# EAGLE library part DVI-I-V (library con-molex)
CONNECTOR MiroCross(TM)-DVI i/0 plug and receptacle connector system (scart)
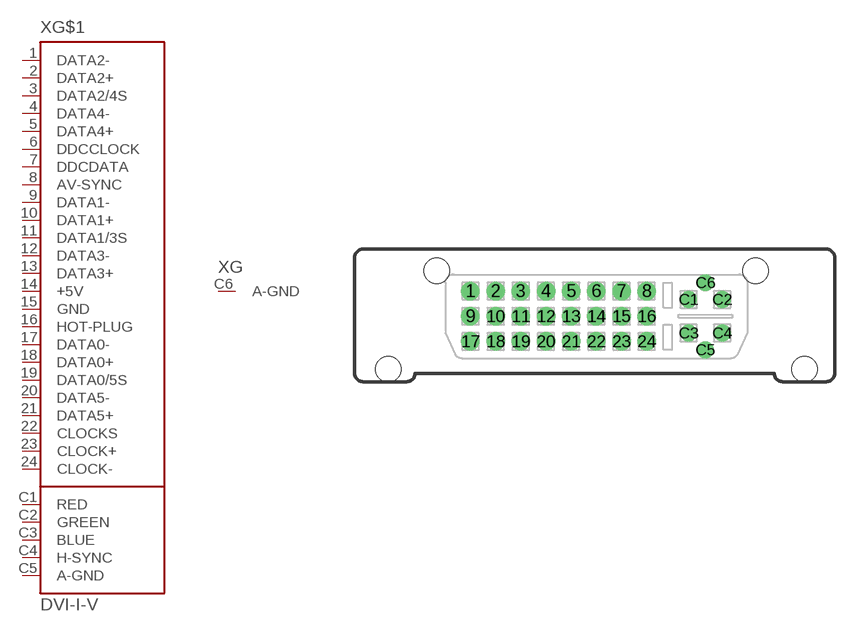
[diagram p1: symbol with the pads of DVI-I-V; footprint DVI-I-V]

Designator prefix X; gates G$1=DVI-I G=AGND

## DVI-I-V (OC_FARNELL: unknown; OC_NEWARK: unknown)  [DVI-I-V]
1  G$1:DATA2-  pas
2  G$1:DATA2+  pas
3  G$1:DATA2/4S  pas
4  G$1:DATA4-  pas
5  G$1:DATA4+  pas
6  G$1:DDCCLOCK  pas
7  G$1:DDCDATA  pas
8  G$1:AV-SYNC  pas
9  G$1:DATA1-  pas
10  G$1:DATA1+  pas
11  G$1:DATA1/3S  pas
12  G$1:DATA3-  pas
13  G$1:DATA3+  pas
14  G$1:+5V  pwr
15  G$1:GND  pwr
16  G$1:HOT-PLUG  pas
17  G$1:DATA0-  pas
18  G$1:DATA0+  pas
19  G$1:DATA0/5S  pas
20  G$1:DATA5-  pas
21  G$1:DATA5+  pas
22  G$1:CLOCKS  pas
23  G$1:CLOCK+  pas
24  G$1:CLOCK-  pas
C1  G$1:RED  pas
C2  G$1:GREEN  pas
C3  G$1:BLUE  pas
C4  G$1:H-SYNC  pas
C5  G$1:A-GND  pwr
C6  G:A-GND  pwr

## Footprint DVI-I-V (pad centres in mm)
CONNECTOR MiroCross(TM)-DVI i/0 plug and receptacle connector system (scart)
drill 0.864 pad 1.397 round: 1 -9.525,1.27; 2 -7.62,1.27; 3 -5.715,1.27; 4 -3.81,1.27; 5 -1.905,1.27; 6 0,1.27; 7 1.905,1.27; 8 3.81,1.27; 9 -9.525,-0.635; 10 -7.62,-0.635; 11 -5.715,-0.635; 12 -3.81,-0.635; 13 -1.905,-0.635; 14 0,-0.635; 15 1.905,-0.635; 16 3.81,-0.635; 17 -9.525,-2.54; 18 -7.62,-2.54; 19 -5.715,-2.54; 20 -3.81,-2.54; 21 -1.905,-2.54; 22 0,-2.54; 23 1.905,-2.54; 24 3.81,-2.54
drill 0.66 pad 1.27 round: C1 6.985,0.635; C2 9.525,0.635; C3 6.985,-1.905; C4 9.525,-1.905; C5 8.255,-3.175; C6 8.255,1.905
hole 1.93 at -12.065,2.794
hole 1.93 at 12.065,2.794
hole 1.93 at -15.748,-4.648
hole 1.93 at 15.748,-4.648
